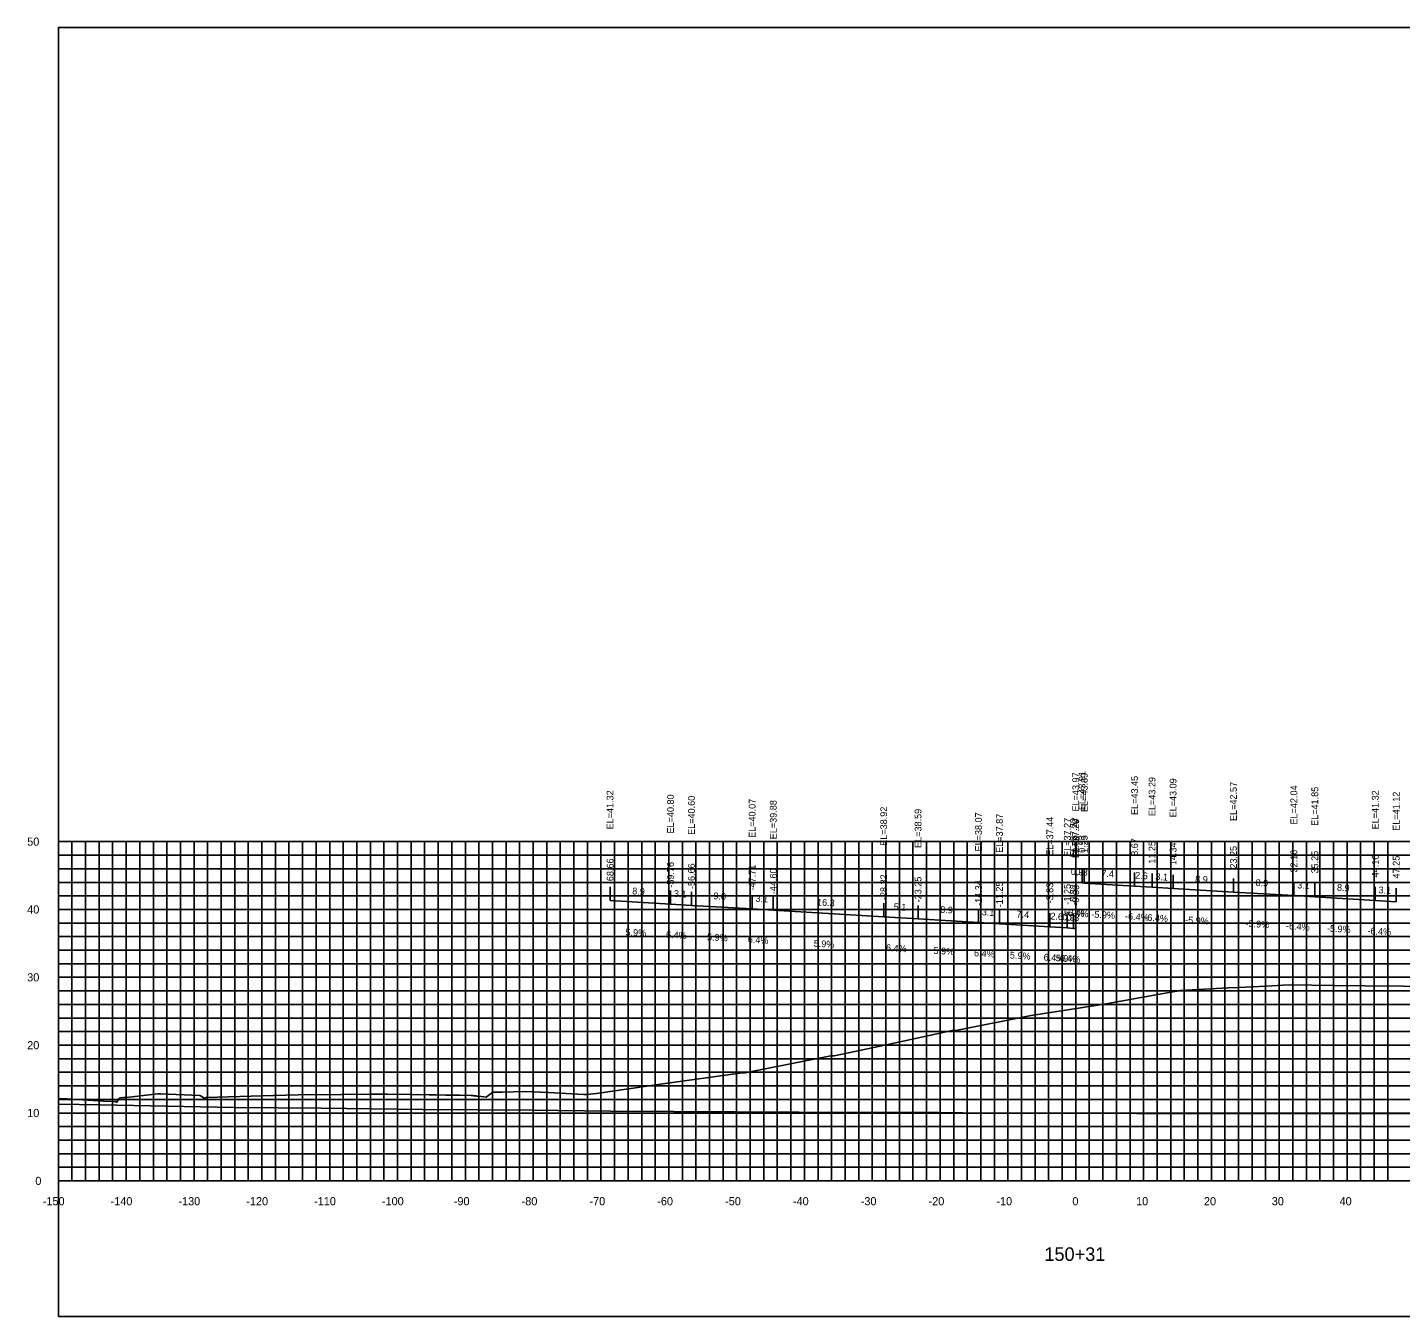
# Model space of a CAD drawing. Extents: x 1800880 to 1818864, y 245271 to 250560.
# Drawn here: x 1810944.2 to 1811146.7, y 247228 to 247418 of the extents above; entities that cross this region are included whole.
import ezdxf

# ---------------------------------------------------------------- set-up
doc = ezdxf.new("R2010")
doc.units = 0
for name, color, linetype in [('33', 7, 'Continuous'), ('ANNO-TXT', 7, 'Continuous'), ('AXIS', 7, 'Continuous'), ('CL-CNST', 7, 'Continuous'), ('DESIGN - DRAINAGE - Bridges', 7, 'Continuous'), ('Level 32', 7, 'Continuous'), ('Level 37', 7, 'Continuous'), ('Level 46', 7, 'Continuous'), ('Level 62', 7, 'Continuous'), ('SHT-BDR', 7, 'Continuous')]:
    doc.layers.add(name, color=color, linetype=linetype)

msp = doc.modelspace()

# ---------------------------------------------------------------- linework, layer by layer
at = {"layer": 'AXIS'}
msp.add_lwpolyline([(1811098.81, 247291.92), (1811099.74, 247291.86), (1811100.06, 247291.84), (1811107.49, 247291.41), (1811110.06, 247291.24), (1811113.16, 247291.04), (1811122.06, 247290.52), (1811130.97, 247290), (1811134.06, 247289.8), (1811142.97, 247289.28), (1811146.06, 247289.08)], dxfattribs=at)
at = {"layer": 'CL-CNST'}
msp.add_lwpolyline([(1810948.81, 247260.07), (1810950.1, 247260.03), (1810950.12, 247260.03), (1810955.47, 247259.71), (1810956.83, 247259.63), (1810957.3, 247259.63), (1810957.33, 247259.63), (1810957.34, 247259.63), (1810957.35, 247259.63), (1810957.37, 247259.52), (1810957.83, 247260.16), (1810957.87, 247260.19), (1810957.92, 247260.19), (1810958.39, 247260.25), (1810958.73, 247260.24), (1810958.83, 247260.25), (1810963.42, 247260.78), (1810963.55, 247260.78), (1810963.93, 247260.78), (1810969.63, 247260.55), (1810969.63, 247260.55), (1810969.63, 247260.55), (1810969.65, 247260.55), (1810969.77, 247260.47), (1810970.3, 247260.13), (1810970.3, 247260.13), (1810970.3, 247260.13), (1810970.31, 247260.13), (1810970.32, 247260.14), (1810970.61, 247260.23), (1810980.53, 247260.53), (1810984.16, 247260.63), (1810990.54, 247260.69), (1810994.69, 247260.73), (1810996.07, 247260.72), (1810997.04, 247260.72), (1810997.12, 247260.72), (1810997.22, 247260.71), (1810997.31, 247260.71), (1810997.37, 247260.7), (1810998.19, 247260.71), (1811003.49, 247260.63), (1811004.51, 247260.62), (1811005.94, 247260.6), (1811008.07, 247260.57), (1811009.66, 247260.54), (1811009.75, 247260.53), (1811009.92, 247260.51), (1811010.06, 247260.5), (1811010.19, 247260.49), (1811010.29, 247260.47), (1811010.39, 247260.46), (1811010.48, 247260.45), (1811010.55, 247260.44), (1811010.62, 247260.44), (1811010.68, 247260.43), (1811010.74, 247260.42), (1811010.79, 247260.42), (1811011.88, 247260.31), (1811012.07, 247260.43), (1811012.54, 247260.78), (1811012.81, 247260.98), (1811012.93, 247261.02), (1811014.19, 247261.02), (1811014.22, 247261.02), (1811017.58, 247261.13), (1811021.09, 247260.99), (1811026.27, 247260.69), (1811026.73, 247260.69), (1811026.77, 247260.69), (1811027.66, 247260.79), (1811028.14, 247260.85), (1811037.92, 247262.26), (1811049.29, 247263.84), (1811049.64, 247263.89), (1811049.68, 247263.89), (1811050.09, 247263.88), (1811052.29, 247264.33), (1811062.69, 247266.38), (1811062.89, 247266.38), (1811063.19, 247266.38), (1811069.99, 247267.81), (1811080.61, 247270.1), (1811080.84, 247270.1), (1811081.14, 247270.11), (1811092.26, 247272.3), (1811103.02, 247274), (1811110.91, 247275.43), (1811114.23, 247276.02), (1811121.33, 247276.39), (1811122.71, 247276.45), (1811124.95, 247276.56), (1811126.8, 247276.65), (1811127.71, 247276.7), (1811129.36, 247276.77), (1811130.32, 247276.82), (1811136.94, 247276.74), (1811141.49, 247276.68), (1811152.8, 247276.58)], dxfattribs=at)
at = {"layer": 'DESIGN - DRAINAGE - Bridges'}
for p, q in [((1810948.75, 247297.95), (1810948.81, 247297.95)), ((1810948.81, 247247.95), (1810948.81, 247297.95)), ((1810948.75, 247287.95), (1810948.81, 247287.95)), ((1810948.75, 247277.95), (1810948.81, 247277.95)), ((1810948.75, 247267.95), (1810948.81, 247267.95)), ((1810948.75, 247257.95), (1810948.81, 247257.95)), ((1810948.75, 247247.95), (1810948.81, 247247.95)), ((1810948.81, 247247.95), (1811248.81, 247247.95)), ((1810948.81, 247247.89), (1810948.81, 247247.95)), ((1810958.81, 247247.89), (1810958.81, 247247.95)), ((1810968.81, 247247.89), (1810968.81, 247247.95)), ((1810978.81, 247247.89), (1810978.81, 247247.95)), ((1810988.81, 247247.89), (1810988.81, 247247.95)), ((1810998.81, 247247.89), (1810998.81, 247247.95)), ((1811008.81, 247247.89), (1811008.81, 247247.95)), ((1811018.81, 247247.89), (1811018.81, 247247.95)), ((1811028.81, 247247.89), (1811028.81, 247247.95)), ((1811038.81, 247247.89), (1811038.81, 247247.95)), ((1811048.81, 247247.89), (1811048.81, 247247.95)), ((1811058.81, 247247.89), (1811058.81, 247247.95)), ((1811068.81, 247247.89), (1811068.81, 247247.95)), ((1811078.81, 247247.89), (1811078.81, 247247.95)), ((1811088.81, 247247.89), (1811088.81, 247247.95)), ((1811098.81, 247247.89), (1811098.81, 247247.95)), ((1811108.81, 247247.89), (1811108.81, 247247.95)), ((1811118.81, 247247.89), (1811118.81, 247247.95)), ((1811128.81, 247247.89), (1811128.81, 247247.95)), ((1811138.81, 247247.89), (1811138.81, 247247.95))]:
    msp.add_line(p, q, dxfattribs=at)
at = {"layer": 'Level 37'}
for p, q in [((1811098.81, 247291.92), (1811098.81, 247293.92)), ((1811099.74, 247291.86), (1811099.74, 247293.86)), ((1811100.06, 247291.84), (1811100.06, 247293.84)), ((1811107.49, 247291.41), (1811107.49, 247293.41)), ((1811110.06, 247291.24), (1811110.06, 247293.24)), ((1811113.16, 247291.04), (1811113.16, 247293.04)), ((1811030.15, 247289.27), (1811030.15, 247291.27)), ((1811122.06, 247290.52), (1811122.06, 247292.52)), ((1811130.97, 247290), (1811130.97, 247292)), ((1811134.06, 247289.8), (1811134.06, 247291.8)), ((1811142.97, 247289.28), (1811142.97, 247291.28)), ((1811146.06, 247289.08), (1811146.06, 247291.08)), ((1811039.06, 247288.75), (1811039.06, 247290.75)), ((1811042.15, 247288.55), (1811042.15, 247290.55)), ((1811051.1, 247288.03), (1811051.1, 247290.03)), ((1811054.21, 247287.83), (1811054.21, 247289.83)), ((1811070.49, 247286.87), (1811070.49, 247288.87)), ((1811075.56, 247286.55), (1811075.56, 247288.55)), ((1811084.47, 247286.02), (1811084.47, 247288.02)), ((1811087.56, 247285.83), (1811087.56, 247287.83)), ((1811094.99, 247285.39), (1811094.99, 247287.39)), ((1811097.56, 247285.22), (1811097.56, 247287.22)), ((1811098.49, 247285.17), (1811098.49, 247287.17)), ((1811098.81, 247285.15), (1811098.81, 247287.15))]:
    msp.add_line(p, q, dxfattribs=at)
msp.add_lwpolyline([(1810948.81, 247227.95), (1811248.81, 247227.95), (1811248.81, 247417.95), (1810948.81, 247417.95)], close=True, dxfattribs=at)
at = {"layer": 'Level 46'}
for p, q in [((1810948.81, 247297.95), (1811248.81, 247297.95)), ((1810948.81, 247247.95), (1810948.81, 247297.95)), ((1810950.81, 247247.95), (1810950.81, 247297.95)), ((1810952.81, 247247.95), (1810952.81, 247297.95)), ((1810954.81, 247247.95), (1810954.81, 247297.95)), ((1810956.81, 247247.95), (1810956.81, 247297.95)), ((1810958.81, 247247.95), (1810958.81, 247297.95)), ((1810960.81, 247247.95), (1810960.81, 247297.95)), ((1810962.81, 247247.95), (1810962.81, 247297.95)), ((1810964.81, 247247.95), (1810964.81, 247297.95)), ((1810966.81, 247247.95), (1810966.81, 247297.95)), ((1810968.81, 247247.95), (1810968.81, 247297.95)), ((1810970.81, 247247.95), (1810970.81, 247297.95)), ((1810972.81, 247247.95), (1810972.81, 247297.95)), ((1810974.81, 247247.95), (1810974.81, 247297.95)), ((1810976.81, 247247.95), (1810976.81, 247297.95)), ((1810978.81, 247247.95), (1810978.81, 247297.95)), ((1810980.81, 247247.95), (1810980.81, 247297.95)), ((1810982.81, 247247.95), (1810982.81, 247297.95)), ((1810984.81, 247247.95), (1810984.81, 247297.95)), ((1810986.81, 247247.95), (1810986.81, 247297.95)), ((1810988.81, 247247.95), (1810988.81, 247297.95)), ((1810990.81, 247247.95), (1810990.81, 247297.95)), ((1810992.81, 247247.95), (1810992.81, 247297.95)), ((1810994.81, 247247.95), (1810994.81, 247297.95)), ((1810996.81, 247247.95), (1810996.81, 247297.95)), ((1810998.81, 247247.95), (1810998.81, 247297.95)), ((1811000.81, 247247.95), (1811000.81, 247297.95)), ((1811002.81, 247247.95), (1811002.81, 247297.95)), ((1811004.81, 247247.95), (1811004.81, 247297.95)), ((1811006.81, 247247.95), (1811006.81, 247297.95)), ((1811008.81, 247247.95), (1811008.81, 247297.95)), ((1811010.81, 247247.95), (1811010.81, 247297.95)), ((1811012.81, 247247.95), (1811012.81, 247297.95)), ((1811014.81, 247247.95), (1811014.81, 247297.95)), ((1811016.81, 247247.95), (1811016.81, 247297.95)), ((1811018.81, 247247.95), (1811018.81, 247297.95)), ((1811020.81, 247247.95), (1811020.81, 247297.95)), ((1811022.81, 247247.95), (1811022.81, 247297.95)), ((1811024.81, 247247.95), (1811024.81, 247297.95)), ((1811026.81, 247247.95), (1811026.81, 247297.95)), ((1811028.81, 247247.95), (1811028.81, 247297.95)), ((1811030.81, 247247.95), (1811030.81, 247297.95)), ((1811032.81, 247247.95), (1811032.81, 247297.95)), ((1811034.81, 247247.95), (1811034.81, 247297.95)), ((1811036.81, 247247.95), (1811036.81, 247297.95)), ((1811038.81, 247247.95), (1811038.81, 247297.95)), ((1811040.81, 247247.95), (1811040.81, 247297.95)), ((1811042.81, 247247.95), (1811042.81, 247297.95)), ((1811044.81, 247247.95), (1811044.81, 247297.95)), ((1811046.81, 247247.95), (1811046.81, 247297.95)), ((1811048.81, 247247.95), (1811048.81, 247297.95)), ((1811050.81, 247247.95), (1811050.81, 247297.95)), ((1811052.81, 247247.95), (1811052.81, 247297.95)), ((1811054.81, 247247.95), (1811054.81, 247297.95)), ((1811056.81, 247247.95), (1811056.81, 247297.95)), ((1811058.81, 247247.95), (1811058.81, 247297.95)), ((1811060.81, 247247.95), (1811060.81, 247297.95)), ((1811062.81, 247247.95), (1811062.81, 247297.95)), ((1811064.81, 247247.95), (1811064.81, 247297.95)), ((1811066.81, 247247.95), (1811066.81, 247297.95)), ((1811068.81, 247247.95), (1811068.81, 247297.95)), ((1811070.81, 247247.95), (1811070.81, 247297.95)), ((1811072.81, 247247.95), (1811072.81, 247297.95)), ((1811074.81, 247247.95), (1811074.81, 247297.95)), ((1811076.81, 247247.95), (1811076.81, 247297.95)), ((1811078.81, 247247.95), (1811078.81, 247297.95)), ((1811080.81, 247247.95), (1811080.81, 247297.95)), ((1811082.81, 247247.95), (1811082.81, 247297.95)), ((1811084.81, 247247.95), (1811084.81, 247297.95)), ((1811086.81, 247247.95), (1811086.81, 247297.95)), ((1811088.81, 247247.95), (1811088.81, 247297.95)), ((1811090.81, 247247.95), (1811090.81, 247297.95)), ((1811092.81, 247247.95), (1811092.81, 247297.95)), ((1811094.81, 247247.95), (1811094.81, 247297.95)), ((1811096.81, 247247.95), (1811096.81, 247297.95)), ((1811098.81, 247247.95), (1811098.81, 247297.95)), ((1811100.81, 247247.95), (1811100.81, 247297.95)), ((1811102.81, 247247.95), (1811102.81, 247297.95)), ((1811104.81, 247247.95), (1811104.81, 247297.95)), ((1811106.81, 247247.95), (1811106.81, 247297.95)), ((1811108.81, 247247.95), (1811108.81, 247297.95)), ((1811110.81, 247247.95), (1811110.81, 247297.95)), ((1811112.81, 247247.95), (1811112.81, 247297.95)), ((1811114.81, 247247.95), (1811114.81, 247297.95)), ((1811116.81, 247247.95), (1811116.81, 247297.95)), ((1811118.81, 247247.95), (1811118.81, 247297.95)), ((1811120.81, 247247.95), (1811120.81, 247297.95)), ((1811122.81, 247247.95), (1811122.81, 247297.95)), ((1811124.81, 247247.95), (1811124.81, 247297.95)), ((1811126.81, 247247.95), (1811126.81, 247297.95)), ((1811128.81, 247247.95), (1811128.81, 247297.95)), ((1811130.81, 247247.95), (1811130.81, 247297.95)), ((1811132.81, 247247.95), (1811132.81, 247297.95)), ((1811134.81, 247247.95), (1811134.81, 247297.95)), ((1811136.81, 247247.95), (1811136.81, 247297.95)), ((1811138.81, 247247.95), (1811138.81, 247297.95)), ((1811140.81, 247247.95), (1811140.81, 247297.95)), ((1811142.81, 247247.95), (1811142.81, 247297.95)), ((1811144.81, 247247.95), (1811144.81, 247297.95)), ((1810948.81, 247295.95), (1811248.81, 247295.95)), ((1810948.81, 247293.95), (1811248.81, 247293.95)), ((1810948.81, 247291.95), (1811248.81, 247291.95)), ((1810948.81, 247289.95), (1811248.81, 247289.95)), ((1810948.81, 247287.95), (1811248.81, 247287.95)), ((1810948.81, 247285.95), (1811248.81, 247285.95)), ((1810948.81, 247283.95), (1811248.81, 247283.95)), ((1810948.81, 247281.95), (1811248.81, 247281.95)), ((1810948.81, 247279.95), (1811248.81, 247279.95)), ((1810948.81, 247277.95), (1811248.81, 247277.95)), ((1810948.81, 247275.95), (1811248.81, 247275.95)), ((1810948.81, 247273.95), (1811248.81, 247273.95)), ((1810948.81, 247271.95), (1811248.81, 247271.95)), ((1810948.81, 247269.95), (1811248.81, 247269.95)), ((1810948.81, 247267.95), (1811248.81, 247267.95)), ((1810948.81, 247265.95), (1811248.81, 247265.95)), ((1810948.81, 247263.95), (1811248.81, 247263.95)), ((1810948.81, 247261.95), (1811248.81, 247261.95)), ((1810948.81, 247259.95), (1811248.81, 247259.95)), ((1810948.81, 247257.95), (1811248.81, 247257.95)), ((1810948.81, 247255.95), (1811248.81, 247255.95)), ((1810948.81, 247253.95), (1811248.81, 247253.95)), ((1810948.81, 247251.95), (1811248.81, 247251.95)), ((1810948.81, 247249.95), (1811248.81, 247249.95)), ((1810948.81, 247247.95), (1811248.81, 247247.95))]:
    msp.add_line(p, q, dxfattribs=at)
at = {"layer": 'Level 62'}
for points in [[(1811030.15, 247289.27), (1811039.06, 247288.75), (1811042.15, 247288.55), (1811051.1, 247288.03), (1811054.21, 247287.83), (1811070.49, 247286.87), (1811075.56, 247286.55), (1811084.47, 247286.02), (1811087.56, 247285.83), (1811094.99, 247285.39), (1811097.56, 247285.22), (1811098.49, 247285.17), (1811098.81, 247285.15)], [(1810948.81, 247259.24), (1810954.95, 247259.18), (1810974.72, 247258.74), (1810987.53, 247258.64), (1811002.47, 247258.45), (1811018.64, 247258.35), (1811030.23, 247258.24), (1811048.88, 247258.14), (1811057.98, 247258.08), (1811078.53, 247258.01), (1811085.74, 247257.94), (1811107.79, 247257.9), (1811113.49, 247257.87), (1811136.77, 247257.87), (1811141.25, 247257.83), (1811165.53, 247257.87), (1811169, 247257.85), (1811194.14, 247257.93), (1811196.76, 247257.92), (1811222.62, 247258.04), (1811224.51, 247258.04), (1811248.81, 247258.18)]]:
    msp.add_lwpolyline(points, dxfattribs=at)

# ---------------------------------------------------------------- texts
for s, p in [('-150', (1810946.51, 247244.35)), ('-140', (1810956.51, 247244.35)), ('-130', (1810966.51, 247244.35)), ('-120', (1810976.51, 247244.35)), ('-110', (1810986.51, 247244.35)), ('-100', (1810996.51, 247244.35)), ('-90', (1811007.11, 247244.35)), ('-80', (1811017.11, 247244.35)), ('-70', (1811027.11, 247244.35)), ('-60', (1811037.11, 247244.35)), ('-50', (1811047.11, 247244.35)), ('-40', (1811057.11, 247244.35)), ('-30', (1811067.11, 247244.35)), ('-20', (1811077.11, 247244.35)), ('-10', (1811087.11, 247244.35)), ('0', (1811098.31, 247244.35)), ('10', (1811107.71, 247244.35)), ('20', (1811117.71, 247244.35)), ('30', (1811127.71, 247244.35)), ('40', (1811137.71, 247244.35))]:
    msp.add_text(s, height=1.2).set_placement(p)
at = {"layer": '33'}
for s, p in [('50', (1810944.21, 247297.35)), ('40', (1810944.21, 247287.35)), ('30', (1810944.21, 247277.35)), ('20', (1810944.21, 247267.35)), ('10', (1810944.21, 247257.35)), ('0', (1810945.41, 247247.35))]:
    msp.add_text(s, height=1.2, dxfattribs=at).set_placement(p)
at = {"layer": 'ANNO-TXT'}
for s, rotation, p in [('0.9', 356.6368, (1811098.06, 247293.06)), ('0.3', 356.3368, (1811098.69, 247293.03)), ('7.4', 356.6368, (1811102.56, 247292.8)), ('2.6', 356.3368, (1811107.54, 247292.51)), ('3.1', 356.3368, (1811110.52, 247292.31)), ('8.9', 356.6368, (1811116.39, 247291.96)), ('8.9', 356.6368, (1811033.39, 247290.19)), ('8.9', 356.6368, (1811125.3, 247291.43)), ('3.1', 356.3368, (1811131.43, 247291.07)), ('8.9', 356.6368, (1811137.3, 247290.71)), ('3.1', 356.3368, (1811143.43, 247290.35)), ('3.1', 356.3368, (1811039.52, 247289.82)), ('9.0', 356.6368, (1811045.37, 247289.47)), ('3.1', 356.3368, (1811051.57, 247289.1)), ('16.3', 356.6368, (1811060.64, 247288.55)), ('5.1', 356.3368, (1811071.94, 247287.88)), ('8.9', 356.6368, (1811078.8, 247287.46)), ('3.1', 356.3368, (1811084.93, 247287.1)), ('7.4', 356.6368, (1811090.06, 247286.78)), ('2.6', 356.3368, (1811095.04, 247286.49)), ('-5.9%', 356.6368, (1811096.58, 247287.04)), ('0.9', 356.6368, (1811096.81, 247286.37)), ('-6.4%', 356.3368, (1811097.18, 247287.02)), ('0.3', 356.3368, (1811097.44, 247286.34)), ('-5.9%', 356.6368, (1811101.08, 247286.77)), ('-6.4%', 356.3368, (1811106.05, 247286.49)), ('-6.4%', 356.3368, (1811108.89, 247286.31)), ('-5.9%', 356.6368, (1811114.91, 247285.93)), ('5.9%', 356.6368, (1811032.4, 247284.13)), ('6.4%', 356.3368, (1811038.37, 247283.78)), ('-5.9%', 356.6368, (1811123.82, 247285.41)), ('-6.4%', 356.3368, (1811129.79, 247285.06)), ('-5.9%', 356.6368, (1811135.82, 247284.69)), ('-6.4%', 356.3368, (1811141.79, 247284.34)), ('5.9%', 356.6368, (1811044.42, 247283.41)), ('6.4%', 356.3368, (1811050.43, 247283.06)), ('5.9%', 356.6368, (1811060.15, 247282.47)), ('6.4%', 356.3368, (1811070.8, 247281.84)), ('5.9%', 356.6368, (1811077.82, 247281.41)), ('6.4%', 356.3368, (1811083.79, 247281.06)), ('5.9%', 356.6368, (1811089.07, 247280.73)), ('6.4%', 356.3368, (1811094.05, 247280.44)), ('5.9%', 356.6368, (1811095.82, 247280.32)), ('6.4%', 356.3368, (1811096.42, 247280.29))]:
    msp.add_text(s, height=1, rotation=rotation, dxfattribs=at).set_placement(p)
at = {"layer": 'DESIGN - DRAINAGE - Bridges'}
for s, height, p in [('>', 1.5, (1811098.21, 247300.2)), ('-', 0.0001, (1810948.81, 247247.95))]:
    msp.add_text(s, height=height, dxfattribs=at).set_placement(p)
at = {"layer": 'Level 32'}
msp.add_text('150+31', height=2, dxfattribs=at).set_placement((1811094.18, 247236.15))
at = {"layer": 'SHT-BDR'}
for s, p in [('EL=43.97', (1811099.31, 247302.39)), ('EL=43.91', (1811100.24, 247302.59)), ('EL=43.89', (1811100.56, 247302.32)), ('EL=43.45', (1811107.99, 247301.88)), ('EL=43.29', (1811110.56, 247301.71)), ('EL=43.09', (1811113.66, 247301.52)), ('EL=41.32', (1811030.65, 247299.75)), ('EL=42.57', (1811122.56, 247300.99)), ('EL=42.04', (1811131.47, 247300.47)), ('EL=41.85', (1811134.56, 247300.27)), ('EL=41.32', (1811143.47, 247299.75)), ('EL=41.12', (1811146.56, 247299.55)), ('EL=40.80', (1811039.56, 247299.15)), ('EL=40.60', (1811042.65, 247298.95)), ('EL=40.07', (1811051.6, 247298.5)), ('EL=39.88', (1811054.71, 247298.3)), ('EL=38.92', (1811070.99, 247297.34)), ('EL=38.59', (1811076.06, 247297.02)), ('EL=38.07', (1811084.97, 247296.5)), ('EL=37.87', (1811088.06, 247296.3)), ('EL=37.44', (1811095.49, 247295.86)), ('EL=37.27', (1811098.06, 247295.7)), ('EL=37.22', (1811098.99, 247295.64)), ('EL=37.20', (1811099.31, 247295.54)), ('0.00', (1811099.31, 247296.28)), ('0.93', (1811100.24, 247296.3)), ('1.25', (1811100.56, 247296.28)), ('8.67', (1811107.99, 247295.85)), ('11.25', (1811110.56, 247294.69)), ('14.34', (1811113.66, 247294.49)), ('23.25', (1811122.56, 247293.97)), ('-68.66', (1811030.65, 247291.68)), ('32.16', (1811131.47, 247293.4)), ('35.25', (1811134.56, 247293.25)), ('44.16', (1811143.47, 247292.68)), ('47.25', (1811146.56, 247292.53)), ('-59.76', (1811039.56, 247291.16)), ('-56.66', (1811042.65, 247290.96)), ('-47.71', (1811051.6, 247290.74)), ('-44.60', (1811054.71, 247290.21)), ('-28.32', (1811070.99, 247289.33)), ('-23.25', (1811076.06, 247289)), ('-14.34', (1811084.97, 247288.48)), ('-11.25', (1811088.06, 247288.28)), ('-3.83', (1811095.49, 247288.84)), ('-1.25', (1811098.06, 247288.67)), ('-0.32', (1811098.99, 247288.62)), ('-0.00', (1811099.31, 247288.52))]:
    msp.add_text(s, height=1, rotation=90, dxfattribs=at).set_placement(p)

doc.saveas('drawing.dxf')
